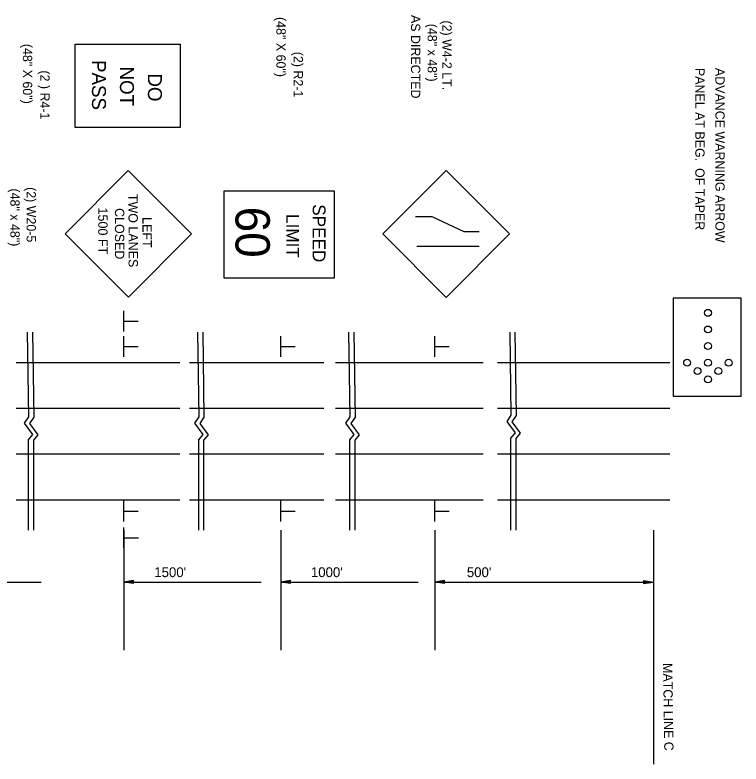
# Model space of a CAD drawing. Extents: x -100 to 745, y -1581 to -107.
# Drawn here: x -6.1 to 42.5, y -553.2 to -503 of the extents above; entities that cross this region are included whole.
import ezdxf

# ---------------------------------------------------------------- set-up
doc = ezdxf.new("R2010")
doc.units = 0
doc.layers.add('Default', color=7, linetype='Continuous')

msp = doc.modelspace()

# ---------------------------------------------------------------- linework, layer by layer
at = {"layer": 'Default'}
for p, q in [((-2.76, -517.687), (1.47, -513.441)), ((1.47, -513.441), (5.712, -517.672)), ((18.523, -517.687), (22.768, -513.442)), ((22.768, -513.442), (27.012, -517.687)), ((20.711, -516.523), (21.792, -516.523)), ((21.792, -516.523), (23.949, -517.513)), ((1.485, -521.917), (-2.76, -517.687)), ((5.712, -517.672), (1.485, -521.917)), ((22.768, -521.931), (18.523, -517.687)), ((27.012, -517.687), (22.768, -521.931)), ((23.949, -517.513), (24.976, -517.513)), ((20.801, -518.503), (24.976, -518.503)), ((1.174, -524.213), (1.174, -522.835)), ((1.195, -523.528), (2.135, -523.528)), ((1.171, -525.914), (1.171, -524.536)), ((11.686, -525.914), (11.686, -524.536)), ((21.993, -525.914), (21.993, -524.536)), ((1.191, -525.229), (2.132, -525.229)), ((11.706, -525.229), (12.647, -525.229)), ((22.013, -525.229), (22.954, -525.229)), ((-6.025, -526.292), (4.936, -526.292)), ((5.579, -526.292), (14.574, -526.292)), ((15.353, -526.292), (25.248, -526.292)), ((26.198, -526.292), (33.749, -526.292)), ((33.749, -526.292), (37.735, -526.292)), ((-6.025, -529.354), (4.936, -529.354)), ((5.579, -529.354), (14.574, -529.354)), ((15.353, -529.354), (25.248, -529.354)), ((26.198, -529.354), (33.749, -529.354)), ((33.749, -529.354), (37.735, -529.354)), ((-6.025, -532.416), (4.936, -532.416)), ((5.579, -532.416), (14.574, -532.416)), ((15.353, -532.416), (25.248, -532.416)), ((26.198, -532.416), (33.749, -532.416)), ((33.749, -532.416), (37.735, -532.416)), ((-6.025, -535.479), (4.936, -535.479)), ((5.579, -535.479), (14.574, -535.479)), ((15.353, -535.479), (25.248, -535.479)), ((26.198, -535.479), (33.749, -535.479)), ((33.749, -535.479), (37.735, -535.479)), ((1.171, -536.936), (1.171, -535.558)), ((11.686, -536.936), (11.686, -535.557)), ((21.993, -536.936), (21.993, -535.557)), ((1.191, -536.25), (2.132, -536.25)), ((11.706, -536.25), (12.647, -536.25)), ((22.013, -536.25), (22.954, -536.25)), ((1.171, -537.506), (1.171, -545.559)), ((1.186, -538.706), (1.186, -537.328)), ((11.686, -537.506), (11.686, -545.559)), ((21.993, -537.506), (21.993, -545.559)), ((36.645, -537.506), (36.645, -553.172)), ((1.207, -538.021), (2.147, -538.021)), ((-13.542, -540.988), (-4.349, -540.988)), ((1.832, -540.889), (1.171, -540.988)), ((1.171, -540.988), (10.364, -540.988)), ((1.832, -541.087), (1.171, -540.988)), ((1.832, -540.905), (1.281, -540.988)), ((1.832, -541.07), (1.281, -540.988)), ((1.832, -540.922), (1.395, -540.988)), ((1.832, -541.053), (1.395, -540.988)), ((1.832, -540.938), (1.505, -540.988)), ((1.832, -541.037), (1.505, -540.988)), ((1.832, -540.955), (1.617, -540.988)), ((1.832, -541.02), (1.617, -540.988)), ((1.832, -540.972), (1.727, -540.988)), ((1.832, -541.003), (1.727, -540.988)), ((1.832, -541.087), (1.832, -540.889)), ((12.347, -540.889), (11.686, -540.988)), ((11.686, -540.988), (20.879, -540.988)), ((12.347, -541.087), (11.686, -540.988)), ((12.347, -540.905), (11.796, -540.988)), ((12.347, -541.07), (11.796, -540.988)), ((12.347, -540.922), (11.91, -540.988)), ((12.347, -541.053), (11.91, -540.988)), ((12.347, -540.938), (12.02, -540.988)), ((12.347, -541.037), (12.02, -540.988)), ((12.347, -540.955), (12.132, -540.988)), ((12.347, -541.02), (12.132, -540.988)), ((12.347, -540.972), (12.242, -540.988)), ((12.347, -541.003), (12.242, -540.988)), ((12.347, -541.087), (12.347, -540.889)), ((22.654, -540.889), (21.993, -540.988)), ((22.654, -541.087), (21.993, -540.988)), ((21.993, -540.988), (36.645, -540.988)), ((22.654, -540.905), (22.104, -540.988)), ((22.654, -541.07), (22.104, -540.988)), ((22.654, -540.922), (22.217, -540.988)), ((22.654, -541.053), (22.217, -540.988)), ((22.654, -540.938), (22.327, -540.988)), ((22.654, -541.037), (22.327, -540.988)), ((22.654, -540.955), (22.439, -540.988)), ((22.654, -541.02), (22.439, -540.988)), ((22.654, -540.972), (22.549, -540.988)), ((22.654, -541.003), (22.549, -540.988)), ((22.654, -541.087), (22.654, -540.889)), ((35.984, -540.889), (36.645, -540.988)), ((35.984, -540.889), (35.984, -541.087)), ((35.984, -540.905), (36.535, -540.988)), ((35.984, -540.922), (36.421, -540.988)), ((35.984, -540.938), (36.311, -540.988)), ((35.984, -540.956), (36.199, -540.988)), ((35.984, -540.972), (36.089, -540.988)), ((35.984, -541.087), (36.645, -540.988)), ((35.984, -541.02), (36.199, -540.988)), ((35.984, -541.053), (36.421, -540.988)), ((35.984, -541.07), (36.535, -540.988)), ((35.984, -541.037), (36.311, -540.988)), ((35.984, -541.003), (36.089, -540.988))]:
    msp.add_line(p, q, dxfattribs=at)
for points in [[(4.947, -510.563), (-2.093, -510.563), (-2.093, -504.978), (4.947, -504.978)], [(15.261, -520.644), (7.894, -520.644), (7.894, -514.8), (15.261, -514.8)], [(37.969, -521.984), (37.969, -528.543), (42.507, -528.543), (42.507, -521.984)]]:
    msp.add_lwpolyline(points, close=True, dxfattribs=at)
for points in [[(-5.293, -524.265), (-5.207, -529.929), (-5.493, -530.355), (-4.935, -531.117), (-5.229, -531.469), (-5.23, -537.506)], [(-4.941, -524.265), (-4.855, -529.944), (-5.141, -530.369), (-4.583, -531.132), (-4.877, -531.484), (-4.878, -537.506)], [(6.105, -524.265), (6.192, -529.929), (5.906, -530.355), (6.463, -531.117), (6.169, -531.469), (6.168, -537.506)], [(6.457, -524.265), (6.543, -529.944), (6.257, -530.369), (6.815, -531.132), (6.521, -531.484), (6.52, -537.506)], [(16.227, -524.265), (16.313, -529.929), (16.027, -530.355), (16.585, -531.117), (16.291, -531.469), (16.29, -537.506)], [(16.579, -524.265), (16.665, -529.944), (16.379, -530.369), (16.936, -531.132), (16.643, -531.484), (16.642, -537.506)], [(27.018, -524.265), (27.102, -529.818), (26.816, -530.243), (27.373, -531.006), (27.08, -531.358), (27.079, -537.506)], [(27.37, -524.265), (27.454, -529.833), (27.168, -530.258), (27.725, -531.021), (27.432, -531.373), (27.431, -537.506)]]:
    msp.add_lwpolyline(points, dxfattribs=at)
for centre in [(40.289, -522.967), (40.289, -524.081), (40.289, -525.194), (38.899, -526.308), (40.289, -526.308), (41.679, -526.308), (39.594, -526.865), (40.984, -526.865), (40.289, -527.422)]:
    msp.add_circle(centre, 0.231, dxfattribs=at)

# ---------------------------------------------------------------- texts
for s, height, rotation, p in [('(48" X 60")', 0.6222, 270, (11.392, -503.164)), ('AS DIRECTED ', 0.6222, 270, (20.405, -503.025)), ('(2) W4-2 LT.', 0.6222, 270, (22.51, -503.392)), ('(48" x 48")', 0.6222, 270, (21.522, -503.614)), ('(48" X 60")', 0.6222, 270, (-5.583, -504.96)), ('(2) R2-1', 0.6222, 270, (12.55, -505.49)), ('PASS', 0.937, 270, (-0.958, -506.043)), ('(2 ) R4-1', 0.6222, 270, (-4.414, -506.737)), ('NOT', 0.9371, 270, (0.916, -506.479)), ('PANEL AT BEG.  OF TAPER', 0.6222, 270, (39.443, -506.571)), ('ADVANCE WARNING ARROW', 0.6222, 270, (40.789, -506.571)), ('DO', 0.9371, 270, (2.79, -506.937)), ('(48" x 48")', 0.6222, 270, (-6.424, -514.642)), ('(2) W20-5', 0.6222, 270, (-5.338, -514.548)), ('TWO LANES', 0.6243, 270.1004, (1.485, -515.005)), ('1500 FT', 0.6283, 270.0006, (-0.541, -515.916)), ('SPEED', 0.857, 270, (13.824, -515.699)), ('CLOSED', 0.6242, 270.1003, (0.577, -515.957)), ('60', 2.2968, 270, (8.653, -515.858)), ('LIMIT', 0.857, 270, (12.053, -516.356)), ('LEFT', 0.6243, 270.1004, (2.424, -516.56)), ('MATCH LINE C', 0.6222, 270.8059, (37.282, -546.418))]:
    msp.add_text(s, height=height, rotation=rotation, dxfattribs=at).set_placement(p)
for s, p in [("1500'", (3.216, -540.662)), ("1000'", (13.704, -540.662)), ("500'", (24.147, -540.662))]:
    msp.add_text(s, height=0.6606, dxfattribs=at).set_placement(p)

doc.saveas('drawing.dxf')
